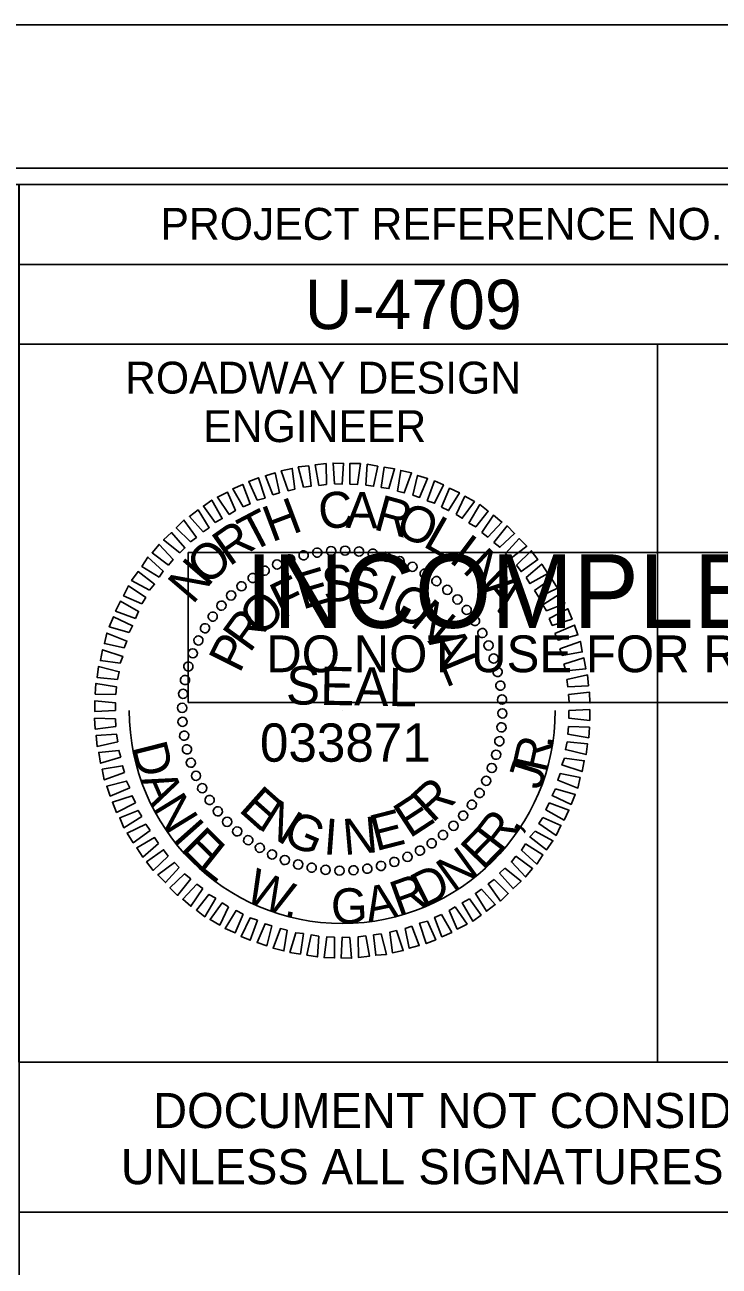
# Model space of a CAD drawing. Extents: x 1779926 to 1781610, y 605564 to 621564.
# Drawn here: x 1781393.9 to 1781502.6, y 606469.7 to 606664.2 of the extents above; entities that cross this region are included whole.
import ezdxf

# ---------------------------------------------------------------- set-up
doc = ezdxf.new("R2010")
doc.units = 0
for name, color, linetype in [('Old_Level_58', 7, 'Continuous'), ('Scratch_Level_0', 7, 'Continuous'), ('Sheet Data Field CELL', 7, 'Continuous'), ('Sheet Plot Border Inside CELL', 7, 'Continuous'), ('Sheet Plot Border Outside CELL', 7, 'Continuous'), ('Sheet Professional Seal CELL', 7, 'Continuous'), ('Sheet Profile CELL', 7, 'Continuous'), ('Sheet Profile Grid Major CELL', 7, 'Continuous'), ('Sheet Profile Grid Minor CELL', 7, 'Continuous'), ('Sheet Sticker Exception Certification CELL', 7, 'Continuous'), ('Sheet Sticker Incomplete CELL', 7, 'Continuous')]:
    doc.layers.add(name, color=color, linetype=linetype)

msp = doc.modelspace()

# ---------------------------------------------------------------- linework, layer by layer
at = {"layer": 'Old_Level_58'}
msp.add_lwpolyline([(1781392.96, 606478.15), (1781592.95, 606478.15), (1781592.95, 606414.2), (1781392.96, 606414.2)], close=True, dxfattribs=at)
at = {"layer": 'Scratch_Level_0'}
msp.add_arc((1781443.6, 606556.73), 33.36, 180, 360, dxfattribs=at)
at = {"layer": 'Sheet Plot Border Inside CELL'}
msp.add_lwpolyline([(1779938.96, 605586.65), (1781605.46, 605586.65), (1781605.46, 606641.75), (1779938.96, 606641.75)], close=True, dxfattribs=at)
at = {"layer": 'Sheet Plot Border Outside CELL'}
msp.add_lwpolyline([(1779925.96, 605564.2), (1781609.96, 605564.2), (1781609.96, 606664.2), (1779925.96, 606664.2)], close=True, dxfattribs=at)
at = {"layer": 'Sheet Professional Seal CELL'}
for p, q in [((1781439.7, 606581.48), (1781439.7, 606581.48)), ((1781441.85, 606581.78), (1781441.85, 606581.78)), ((1781444.05, 606581.83), (1781444.05, 606581.83)), ((1781446.25, 606581.68), (1781446.25, 606581.68)), ((1781448.4, 606581.33), (1781448.4, 606581.33)), ((1781433.4, 606579.68), (1781433.4, 606579.68)), ((1781435.4, 606580.48), (1781435.4, 606580.48)), ((1781437.5, 606581.08), (1781437.5, 606581.08)), ((1781450.5, 606580.88), (1781450.5, 606580.88)), ((1781452.6, 606580.18), (1781452.6, 606580.18)), ((1781429.55, 606577.53), (1781429.55, 606577.53)), ((1781431.45, 606578.68), (1781431.45, 606578.68)), ((1781454.6, 606579.28), (1781454.6, 606579.28)), ((1781456.55, 606578.28), (1781456.55, 606578.28)), ((1781427.8, 606576.28), (1781427.8, 606576.28)), ((1781458.35, 606577.03), (1781458.35, 606577.03)), ((1781460.1, 606575.68), (1781460.1, 606575.68)), ((1781426.15, 606574.78), (1781426.15, 606574.78)), ((1781461.65, 606574.18), (1781461.65, 606574.18)), ((1781424.65, 606573.23), (1781424.65, 606573.23)), ((1781463.15, 606572.53), (1781463.15, 606572.53)), ((1781422.05, 606569.68), (1781422.05, 606569.68)), ((1781423.3, 606571.48), (1781423.3, 606571.48)), ((1781464.4, 606570.78), (1781464.4, 606570.78)), ((1781421.05, 606567.73), (1781421.05, 606567.73)), ((1781465.55, 606568.88), (1781465.55, 606568.88)), ((1781420.15, 606565.73), (1781420.15, 606565.73)), ((1781466.55, 606566.93), (1781466.55, 606566.93)), ((1781467.35, 606564.93), (1781467.35, 606564.93)), ((1781419.45, 606563.63), (1781419.45, 606563.63)), ((1781467.95, 606562.83), (1781467.95, 606562.83)), ((1781419, 606561.53), (1781419, 606561.53)), ((1781468.35, 606560.63), (1781468.35, 606560.63)), ((1781418.65, 606559.38), (1781418.65, 606559.38)), ((1781468.65, 606558.48), (1781468.65, 606558.48)), ((1781418.5, 606557.18), (1781418.5, 606557.18)), ((1781443.6, 606556.73), (1781443.6, 606556.73)), ((1781468.7, 606556.28), (1781468.7, 606556.28)), ((1781418.55, 606554.98), (1781418.55, 606554.98)), ((1781468.55, 606554.08), (1781468.55, 606554.08)), ((1781418.85, 606552.83), (1781418.85, 606552.83)), ((1781419.25, 606550.63), (1781419.25, 606550.63)), ((1781468.2, 606551.93), (1781468.2, 606551.93)), ((1781419.85, 606548.53), (1781419.85, 606548.53)), ((1781467.75, 606549.83), (1781467.75, 606549.83)), ((1781420.65, 606546.53), (1781420.65, 606546.53)), ((1781467.05, 606547.73), (1781467.05, 606547.73)), ((1781421.65, 606544.58), (1781421.65, 606544.58)), ((1781466.15, 606545.73), (1781466.15, 606545.73)), ((1781422.8, 606542.68), (1781422.8, 606542.68)), ((1781465.15, 606543.78), (1781465.15, 606543.78)), ((1781424.05, 606540.93), (1781424.05, 606540.93)), ((1781463.9, 606541.98), (1781463.9, 606541.98)), ((1781425.55, 606539.28), (1781425.55, 606539.28)), ((1781461.05, 606538.68), (1781461.05, 606538.68)), ((1781462.55, 606540.23), (1781462.55, 606540.23)), ((1781427.1, 606537.78), (1781427.1, 606537.78)), ((1781459.4, 606537.18), (1781459.4, 606537.18)), ((1781428.85, 606536.43), (1781428.85, 606536.43)), ((1781430.65, 606535.18), (1781430.65, 606535.18)), ((1781455.75, 606534.78), (1781455.75, 606534.78)), ((1781457.65, 606535.93), (1781457.65, 606535.93)), ((1781432.6, 606534.18), (1781432.6, 606534.18)), ((1781434.6, 606533.28), (1781434.6, 606533.28)), ((1781451.8, 606532.98), (1781451.8, 606532.98)), ((1781453.8, 606533.78), (1781453.8, 606533.78)), ((1781436.7, 606532.58), (1781436.7, 606532.58)), ((1781438.8, 606532.13), (1781438.8, 606532.13)), ((1781440.95, 606531.78), (1781440.95, 606531.78)), ((1781443.15, 606531.63), (1781443.15, 606531.63)), ((1781445.35, 606531.68), (1781445.35, 606531.68)), ((1781447.5, 606531.98), (1781447.5, 606531.98)), ((1781449.7, 606532.38), (1781449.7, 606532.38))]:
    msp.add_line(p, q, dxfattribs=at)
for points in [[(1781437.5, 606591.73), (1781436.7, 606594.93), (1781438.35, 606595.08), (1781438.7, 606591.88)], [(1781439.9, 606592.03), (1781439.35, 606595.23), (1781441.05, 606595.43), (1781441.1, 606592.18)], [(1781442.4, 606592.28), (1781442.15, 606595.53), (1781443.8, 606595.48), (1781443.6, 606592.23)], [(1781444.8, 606592.23), (1781444.8, 606595.48), (1781446.45, 606595.43), (1781446, 606592.18)], [(1781447.3, 606592.08), (1781447.5, 606595.33), (1781449.15, 606595.03), (1781448.5, 606591.88)], [(1781430.25, 606589.73), (1781428.95, 606592.63), (1781430.45, 606593.23), (1781431.5, 606590.03)], [(1781432.7, 606590.53), (1781431.55, 606593.53), (1781433.1, 606593.98), (1781433.75, 606590.88)], [(1781435.1, 606591.18), (1781434.05, 606594.33), (1781435.75, 606594.68), (1781436.15, 606591.43)], [(1781449.7, 606591.68), (1781450.15, 606594.88), (1781451.8, 606594.63), (1781450.9, 606591.53)], [(1781452.25, 606591.13), (1781452.75, 606594.38), (1781454.45, 606593.98), (1781453.3, 606590.88)], [(1781454.65, 606590.48), (1781455.4, 606593.58), (1781456.95, 606593.08), (1781455.7, 606590.13)], [(1781428.05, 606588.68), (1781426.45, 606591.48), (1781428, 606592.18), (1781429.15, 606589.13)], [(1781456.9, 606589.58), (1781458.05, 606592.73), (1781459.45, 606592.13), (1781458.05, 606589.23)], [(1781459.15, 606588.63), (1781460.4, 606591.58), (1781461.95, 606590.88), (1781460.25, 606588.08)], [(1781423.7, 606586.23), (1781421.85, 606588.78), (1781423.15, 606589.73), (1781424.8, 606586.83)], [(1781425.9, 606587.48), (1781424.05, 606590.18), (1781425.6, 606590.98), (1781426.85, 606588.08)], [(1781461.45, 606587.48), (1781462.8, 606590.33), (1781464.3, 606589.48), (1781462.4, 606586.88)], [(1781421.8, 606584.73), (1781419.65, 606587.13), (1781421, 606588.18), (1781422.75, 606585.38)], [(1781463.4, 606586.13), (1781465.15, 606589.03), (1781466.45, 606587.98), (1781464.5, 606585.53)], [(1781465.45, 606584.63), (1781467.3, 606587.38), (1781468.6, 606586.28), (1781466.4, 606583.93)], [(1781419.8, 606583.18), (1781417.6, 606585.38), (1781418.8, 606586.58), (1781420.75, 606583.88)], [(1781467.35, 606583.08), (1781469.4, 606585.68), (1781470.6, 606584.48), (1781468.3, 606582.33)], [(1781418.15, 606581.43), (1781415.6, 606583.48), (1781416.85, 606584.63), (1781418.95, 606582.23)], [(1781469.15, 606581.33), (1781471.3, 606583.68), (1781472.5, 606582.48), (1781469.9, 606580.53)], [(1781416.4, 606579.53), (1781413.8, 606581.48), (1781414.9, 606582.78), (1781417.1, 606580.43)], [(1781470.9, 606579.53), (1781473.2, 606581.78), (1781474.25, 606580.43), (1781471.6, 606578.53)], [(1781414.9, 606577.63), (1781412.2, 606579.33), (1781413.15, 606580.78), (1781415.55, 606578.58)], [(1781472.4, 606577.58), (1781474.85, 606579.68), (1781475.8, 606578.23), (1781473, 606576.63)], [(1781413.4, 606575.63), (1781410.6, 606577.13), (1781411.6, 606578.53), (1781414.2, 606576.53)], [(1781473.7, 606575.53), (1781476.35, 606577.43), (1781477.3, 606575.93), (1781474.4, 606574.53)], [(1781412.2, 606573.48), (1781409.35, 606574.73), (1781410.1, 606576.28), (1781412.8, 606574.43)], [(1781411.2, 606571.18), (1781408.1, 606572.33), (1781408.85, 606573.88), (1781411.7, 606572.28)], [(1781475, 606573.33), (1781477.8, 606575.08), (1781478.45, 606573.53), (1781475.6, 606572.38)], [(1781476, 606571.18), (1781478.95, 606572.68), (1781479.6, 606571.08), (1781476.5, 606570.08)], [(1781410.2, 606568.98), (1781407.1, 606569.88), (1781407.75, 606571.43), (1781410.75, 606570.03)], [(1781476.9, 606568.83), (1781479.95, 606570.13), (1781480.5, 606568.58), (1781477.4, 606567.78)], [(1781409.45, 606566.58), (1781406.35, 606567.23), (1781406.7, 606568.88), (1781409.85, 606567.63)], [(1781408.8, 606564.18), (1781405.7, 606564.58), (1781406.05, 606566.28), (1781409.2, 606565.23)], [(1781477.7, 606566.43), (1781480.9, 606567.58), (1781481.2, 606565.93), (1781478.05, 606565.38)], [(1781478.3, 606564.03), (1781481.45, 606564.98), (1781481.75, 606563.28), (1781478.6, 606562.98)], [(1781408.4, 606561.63), (1781405.2, 606561.93), (1781405.4, 606563.63), (1781408.65, 606562.83)], [(1781478.75, 606561.63), (1781482, 606562.33), (1781482.15, 606560.63), (1781478.95, 606560.43)], [(1781408.15, 606559.23), (1781404.9, 606559.33), (1781405, 606560.98), (1781408.25, 606560.43)], [(1781408.1, 606556.73), (1781404.85, 606556.58), (1781404.85, 606558.28), (1781408.1, 606557.93)], [(1781479.05, 606559.23), (1781482.3, 606559.63), (1781482.4, 606557.93), (1781479.15, 606558.03)], [(1781479.1, 606556.73), (1781482.35, 606556.88), (1781482.35, 606555.18), (1781479.1, 606555.53)], [(1781408.15, 606554.23), (1781404.9, 606553.83), (1781404.8, 606555.53), (1781408.05, 606555.43)], [(1781479.05, 606554.23), (1781482.3, 606554.13), (1781482.2, 606552.48), (1781478.95, 606553.03)], [(1781408.45, 606551.83), (1781405.2, 606551.13), (1781405.05, 606552.83), (1781408.25, 606553.03)], [(1781408.9, 606549.43), (1781405.75, 606548.48), (1781405.45, 606550.18), (1781408.6, 606550.48)], [(1781478.8, 606551.83), (1781482, 606551.53), (1781481.8, 606549.83), (1781478.55, 606550.63)], [(1781478.4, 606549.28), (1781481.5, 606548.88), (1781481.15, 606547.18), (1781478, 606548.23)], [(1781409.5, 606547.03), (1781406.3, 606545.88), (1781406, 606547.53), (1781409.15, 606548.08)], [(1781477.75, 606546.88), (1781480.85, 606546.23), (1781480.5, 606544.58), (1781477.35, 606545.83)], [(1781410.3, 606544.63), (1781407.25, 606543.33), (1781406.7, 606544.88), (1781409.8, 606545.68)], [(1781477, 606544.48), (1781480.1, 606543.58), (1781479.45, 606542.03), (1781476.45, 606543.43)], [(1781411.2, 606542.28), (1781408.25, 606540.78), (1781407.6, 606542.38), (1781410.7, 606543.38)], [(1781412.2, 606540.13), (1781409.4, 606538.38), (1781408.75, 606539.93), (1781411.6, 606541.08)], [(1781476, 606542.28), (1781479.1, 606541.13), (1781478.35, 606539.58), (1781475.5, 606541.18)], [(1781413.5, 606537.93), (1781410.85, 606536.03), (1781409.9, 606537.53), (1781412.8, 606538.93)], [(1781475, 606539.98), (1781477.85, 606538.73), (1781477.1, 606537.18), (1781474.4, 606539.03)], [(1781414.8, 606535.88), (1781412.35, 606533.78), (1781411.4, 606535.23), (1781414.2, 606536.83)], [(1781473.8, 606537.83), (1781476.6, 606536.33), (1781475.6, 606534.93), (1781473, 606536.93)], [(1781416.3, 606533.93), (1781414, 606531.68), (1781412.95, 606533.03), (1781415.6, 606534.93)], [(1781472.3, 606535.83), (1781475, 606534.13), (1781474.05, 606532.68), (1781471.65, 606534.88)], [(1781418.05, 606532.13), (1781415.9, 606529.78), (1781414.7, 606530.98), (1781417.3, 606532.93)], [(1781470.8, 606533.93), (1781473.4, 606531.98), (1781472.3, 606530.68), (1781470.1, 606533.03)], [(1781419.85, 606530.38), (1781417.8, 606527.78), (1781416.6, 606528.98), (1781418.9, 606531.13)], [(1781469.05, 606532.03), (1781471.6, 606529.98), (1781470.35, 606528.83), (1781468.25, 606531.23)], [(1781421.75, 606528.83), (1781419.9, 606526.08), (1781418.6, 606527.18), (1781420.8, 606529.53)], [(1781467.4, 606530.28), (1781469.6, 606528.08), (1781468.4, 606526.88), (1781466.45, 606529.58)], [(1781423.8, 606527.33), (1781422.05, 606524.43), (1781420.75, 606525.48), (1781422.7, 606527.93)], [(1781463.5, 606527.23), (1781465.35, 606524.68), (1781464.05, 606523.73), (1781462.4, 606526.63)], [(1781465.4, 606528.73), (1781467.55, 606526.33), (1781466.2, 606525.28), (1781464.45, 606528.08)], [(1781425.75, 606525.98), (1781424.4, 606523.13), (1781422.9, 606523.98), (1781424.8, 606526.58)], [(1781428.05, 606524.83), (1781426.8, 606521.88), (1781425.25, 606522.58), (1781426.95, 606525.38)], [(1781461.3, 606525.98), (1781463.15, 606523.28), (1781461.6, 606522.48), (1781460.35, 606525.38)], [(1781430.3, 606523.88), (1781429.15, 606520.73), (1781427.75, 606521.33), (1781429.15, 606524.23)], [(1781432.55, 606522.98), (1781431.8, 606519.88), (1781430.25, 606520.38), (1781431.5, 606523.33)], [(1781454.5, 606522.93), (1781455.65, 606519.93), (1781454.1, 606519.48), (1781453.45, 606522.58)], [(1781456.95, 606523.73), (1781458.25, 606520.83), (1781456.75, 606520.23), (1781455.7, 606523.43)], [(1781459.15, 606524.78), (1781460.75, 606521.98), (1781459.2, 606521.28), (1781458.05, 606524.33)], [(1781434.95, 606522.33), (1781434.45, 606519.08), (1781432.75, 606519.48), (1781433.9, 606522.58)], [(1781437.5, 606521.78), (1781437.05, 606518.58), (1781435.4, 606518.83), (1781436.3, 606521.93)], [(1781439.9, 606521.38), (1781439.7, 606518.13), (1781438.05, 606518.43), (1781438.7, 606521.58)], [(1781442.4, 606521.23), (1781442.4, 606517.98), (1781440.75, 606518.03), (1781441.2, 606521.28)], [(1781444.8, 606521.18), (1781445.05, 606517.93), (1781443.4, 606517.98), (1781443.6, 606521.23)], [(1781447.3, 606521.43), (1781447.85, 606518.23), (1781446.15, 606518.03), (1781446.1, 606521.28)], [(1781449.7, 606521.73), (1781450.5, 606518.53), (1781448.85, 606518.38), (1781448.5, 606521.58)], [(1781452.1, 606522.28), (1781453.15, 606519.13), (1781451.45, 606518.78), (1781451.05, 606522.03)]]:
    msp.add_lwpolyline(points, close=True, dxfattribs=at)
for centre, major_axis in [((1781437.53, 606581.06), (-0.174, 0.699)), ((1781439.67, 606581.5), (-0.113, 0.711)), ((1781441.85, 606581.74), (-0.05, 0.718)), ((1781444.04, 606581.8), (0.013, 0.72)), ((1781446.22, 606581.67), (0.075, 0.716)), ((1781448.38, 606581.34), (0.137, 0.707)), ((1781450.51, 606580.83), (0.198, 0.692)), ((1781431.44, 606578.66), (-0.349, 0.63)), ((1781433.4, 606579.64), (-0.293, 0.658)), ((1781435.43, 606580.44), (-0.234, 0.681)), ((1781452.59, 606580.14), (0.258, 0.672)), ((1781454.59, 606579.27), (0.316, 0.647)), ((1781429.57, 606577.52), (-0.403, 0.597)), ((1781456.51, 606578.22), (0.371, 0.617)), ((1781458.34, 606577.02), (0.423, 0.582)), ((1781426.18, 606574.77), (-0.5, 0.518)), ((1781427.81, 606576.22), (-0.453, 0.56)), ((1781460.05, 606575.65), (0.472, 0.543)), ((1781424.67, 606573.18), (-0.543, 0.472)), ((1781461.64, 606574.15), (0.518, 0.5)), ((1781423.31, 606571.47), (-0.582, 0.423)), ((1781463.09, 606572.51), (0.56, 0.453)), ((1781464.39, 606570.75), (0.597, 0.403)), ((1781422.1, 606569.64), (-0.617, 0.371)), ((1781465.53, 606568.88), (0.63, 0.349)), ((1781421.06, 606567.72), (-0.647, 0.316)), ((1781466.51, 606566.93), (0.658, 0.293)), ((1781420.18, 606565.71), (-0.672, 0.258)), ((1781419.49, 606563.64), (-0.692, 0.198)), ((1781467.31, 606564.89), (0.681, 0.234)), ((1781418.98, 606561.51), (-0.707, 0.137)), ((1781467.93, 606562.79), (0.699, 0.174)), ((1781418.66, 606559.35), (-0.716, 0.075)), ((1781468.37, 606560.65), (0.711, 0.113)), ((1781468.62, 606558.47), (0.718, 0.05)), ((1781418.52, 606557.16), (-0.72, 0.013)), ((1781468.67, 606556.29), (0.72, -0.013)), ((1781418.58, 606554.98), (-0.718, -0.05)), ((1781468.54, 606554.1), (0.716, -0.075)), ((1781418.83, 606552.8), (-0.711, -0.113)), ((1781468.22, 606551.94), (0.707, -0.137)), ((1781419.26, 606550.66), (-0.699, -0.174)), ((1781467.71, 606549.81), (0.692, -0.198)), ((1781419.88, 606548.56), (-0.681, -0.234)), ((1781467.01, 606547.74), (0.672, -0.258)), ((1781420.69, 606546.52), (-0.658, -0.293)), ((1781466.14, 606545.73), (0.647, -0.316)), ((1781421.66, 606544.57), (-0.63, -0.349)), ((1781465.1, 606543.81), (0.617, -0.371)), ((1781422.81, 606542.7), (-0.597, -0.403)), ((1781463.89, 606541.98), (0.582, -0.423)), ((1781424.11, 606540.94), (-0.56, -0.453)), ((1781462.53, 606540.27), (0.543, -0.472)), ((1781425.56, 606539.3), (-0.518, -0.5)), ((1781427.14, 606537.8), (-0.472, -0.543)), ((1781461.02, 606538.68), (0.5, -0.518)), ((1781428.86, 606536.43), (-0.423, -0.582)), ((1781457.62, 606535.93), (0.403, -0.597)), ((1781459.38, 606537.23), (0.453, -0.56)), ((1781430.68, 606535.23), (-0.371, -0.617)), ((1781432.6, 606534.18), (-0.316, -0.647)), ((1781453.8, 606533.81), (0.293, -0.658)), ((1781455.76, 606534.79), (0.349, -0.63)), ((1781434.61, 606533.31), (-0.258, -0.672)), ((1781436.68, 606532.62), (-0.198, -0.692)), ((1781438.81, 606532.11), (-0.137, -0.707)), ((1781447.52, 606531.95), (0.113, -0.711)), ((1781449.67, 606532.39), (0.174, -0.699)), ((1781451.76, 606533.01), (0.234, -0.681)), ((1781440.98, 606531.78), (-0.075, -0.716)), ((1781443.16, 606531.65), (-0.013, -0.72)), ((1781445.35, 606531.71), (0.05, -0.718))]:
    msp.add_ellipse(centre, major_axis=major_axis, ratio=0.999708, dxfattribs=at)
at = {"layer": 'Sheet Profile CELL'}
for p, q in [((1781392.91, 606626.65), (1781592.96, 606626.65)), ((1781492.96, 606614.15), (1781492.96, 606501.7))]:
    msp.add_line(p, q, dxfattribs=at)
for points in [[(1781592.96, 606639.2), (1780092.96, 606639.2), (1780092.96, 605589.2), (1781592.96, 605589.2)], [(1781392.91, 606639.2), (1781592.96, 606639.2), (1781592.96, 606614.15), (1781392.91, 606614.15)], [(1781392.91, 606614.15), (1781492.96, 606614.15), (1781492.96, 606501.65), (1781392.91, 606501.65)], [(1781492.96, 606614.15), (1781592.96, 606614.15), (1781592.96, 606501.65), (1781492.96, 606501.65)]]:
    msp.add_lwpolyline(points, close=True, dxfattribs=at)
at = {"layer": 'Sheet Profile Grid Major CELL'}
msp.add_lwpolyline([(1780942.96, 606139.2), (1780992.96, 606139.2), (1780992.96, 606639.2), (1781042.96, 606639.2), (1781042.96, 606139.2), (1781092.96, 606139.2), (1781092.96, 606639.2), (1781142.96, 606639.2), (1781142.96, 606139.2), (1781192.96, 606139.2), (1781192.96, 606639.2), (1781242.96, 606639.2), (1781242.96, 606139.2), (1781292.96, 606139.2), (1781292.96, 606639.2), (1781342.96, 606639.2), (1781342.96, 606139.2), (1781392.96, 606139.2), (1781392.96, 606639.2), (1781419.26, 606639.2)], dxfattribs=at)
at = {"layer": 'Sheet Profile Grid Minor CELL'}
msp.add_lwpolyline([(1781387.96, 606639.2), (1781397.96, 606639.2)], dxfattribs=at)
at = {"layer": 'Sheet Sticker Exception Certification CELL'}
for p, q in [((1781392.91, 606501.65), (1781592.95, 606501.65)), ((1781392.91, 606501.65), (1781592.95, 606501.65)), ((1781592.95, 606478.15), (1781392.91, 606478.15)), ((1781592.95, 606478.15), (1781392.91, 606478.15))]:
    msp.add_line(p, q, dxfattribs=at)
at = {"layer": 'Sheet Sticker Incomplete CELL'}
msp.add_lwpolyline([(1781419.48, 606558), (1781419.48, 606581.5), (1781566.48, 606581.5), (1781566.48, 606558)], close=True, dxfattribs=at)

# ---------------------------------------------------------------- texts
at = {"layer": 'Sheet Data Field CELL'}
msp.add_text('U-4709', height=7.75, dxfattribs=at).set_placement((1781437.72, 606616.51))
at = {"layer": 'Sheet Professional Seal CELL'}
for s, height, rotation, p in [('C', 5.64, 6.2199, (1781440.15, 606585.08)), ('H', 5.64, 20.6195, (1781432.55, 606583.08)), ('A', 5.64, 359.0203, (1781444.1, 606585.38)), ('R', 5.64, 344.6211, (1781448.3, 606585.18)), ('T', 5.64, 27.8198, (1781429.3, 606581.43)), ('O', 5.64, 337.4212, (1781451.65, 606584.43)), ('L', 5.64, 330.2209, (1781456.05, 606582.58)), ('R', 5.64, 35.0205, (1781425.9, 606579.23)), ('I', 5.64, 323.0201, (1781460.1, 606580.18)), ('O', 5.64, 42.2217, (1781422.45, 606576.13)), ('N', 5.64, 315.8189, (1781462.25, 606578.63)), ('N', 5.64, 49.4235, (1781420.15, 606573.23)), ('S', 5.64, 7.2556, (1781440.8, 606573.58)), ('F', 5.64, 25.967, (1781434.15, 606571.03)), ('E', 5.64, 16.6111, (1781437.35, 606572.53)), ('S', 5.64, 357.9004, (1781444.4, 606573.63)), ('I', 5.64, 339.1896, (1781448.7, 606572.93)), ('A', 5.64, 308.6172, (1781465.2, 606575.68)), ('O', 5.64, 329.8335, (1781450.7, 606572.23)), ('O', 5.64, 44.6812, (1781430.85, 606568.08)), ('N', 5.64, 320.4766, (1781454.05, 606570.23)), ('R', 5.64, 54.0397, (1781429.1, 606565.63)), ('P', 5.64, 63.3989, (1781427.5, 606562.43)), ('A', 5.64, 301.7603, (1781456.9, 606567.63)), ('L', 5.64, 292.4008, (1781458.85, 606564.18)), ('SEAL', 5.998, 359, (1781434.75, 606557.73)), ('E', 5.64, 318.2769, (1781427.2, 606541.08)), ('R', 5.64, 42.4814, (1781457.7, 606538.98)), ('N', 5.64, 327.634, (1781430.2, 606538.38)), ('E', 5.64, 33.1241, (1781454.15, 606536.63)), ('G', 5.64, 336.9902, (1781434, 606536.13)), ('E', 5.64, 14.4118, (1781448.85, 606534.68)), ('I', 5.64, 355.7012, (1781440.55, 606534.23)), ('N', 5.64, 5.0564, (1781443.9, 606534.08))]:
    msp.add_text(s, height=height, rotation=rotation, dxfattribs=at).set_placement(p)
at = {"layer": 'Sheet Profile CELL'}
for s, height, p in [('PROJECT REFERENCE NO.', 5.0001, (1781415.12, 606630.51)), ('ROADWAY DESIGN', 5.0001, (1781409.57, 606606.41)), ('ENGINEER', 5, (1781421.82, 606598.81))]:
    msp.add_text(s, height=height, dxfattribs=at).set_placement(p)
at = {"layer": 'Sheet Profile Grid Minor CELL'}
msp.add_text('033871', height=5.998, dxfattribs=at).set_placement((1781430.7, 606548.72))
for s, rotation, p in [('R', 77.3541, (1781475.57, 606546.82)), ('.', 84.2805, (1781476.53, 606550.75)), ('D', 284.2682, (1781410.61, 606551.08)), ('J', 72.4855, (1781474.61, 606544.15)), ('A', 293.4128, (1781411.92, 606545.91)), ('N', 301.5986, (1781413.79, 606541.51)), ('R', 52.3788, (1781468.4, 606534.25)), ('I', 311.5304, (1781416.86, 606536.6)), ('E', 45.7958, (1781465.66, 606531.55)), (',', 59.3052, (1781470.93, 606537.4)), ('E', 315.0508, (1781418.14, 606534.99)), ('L', 321.6338, (1781420.8, 606532.22)), ('N', 35.8641, (1781460.99, 606528.13)), ('W', 336.8891, (1781428.05, 606527.08)), ('R', 19.793, (1781452.39, 606524.43)), ('D', 26.7195, (1781456.22, 606525.73)), ('G', 1.6755, (1781441.91, 606523.3)), ('A', 11.6072, (1781447.7, 606523.51)), ('.', 348.4952, (1781434.33, 606524.56))]:
    msp.add_text(s, height=5.5, rotation=rotation, dxfattribs=at).set_placement(p)
at = {"layer": 'Sheet Sticker Exception Certification CELL'}
for s, p in [('DOCUMENT NOT CONSIDERED FINAL', (1781413.98, 606491.31)), ('DOCUMENT NOT CONSIDERED FINAL', (1781413.98, 606491.31)), ('UNLESS ALL SIGNATURES COMPLETED', (1781408.91, 606482.51)), ('UNLESS ALL SIGNATURES COMPLETED', (1781408.91, 606482.51))]:
    msp.add_text(s, height=5.5, dxfattribs=at).set_placement(p)
at = {"layer": 'Sheet Sticker Incomplete CELL'}
for s, height, p in [('INCOMPLETE PLANS', 11.52, (1781428.43, 606569.7)), ('DO NOT USE FOR R/W ACQUISITION', 5.76, (1781431.68, 606562.75))]:
    msp.add_text(s, height=height, dxfattribs=at).set_placement(p)

doc.saveas('drawing.dxf')
